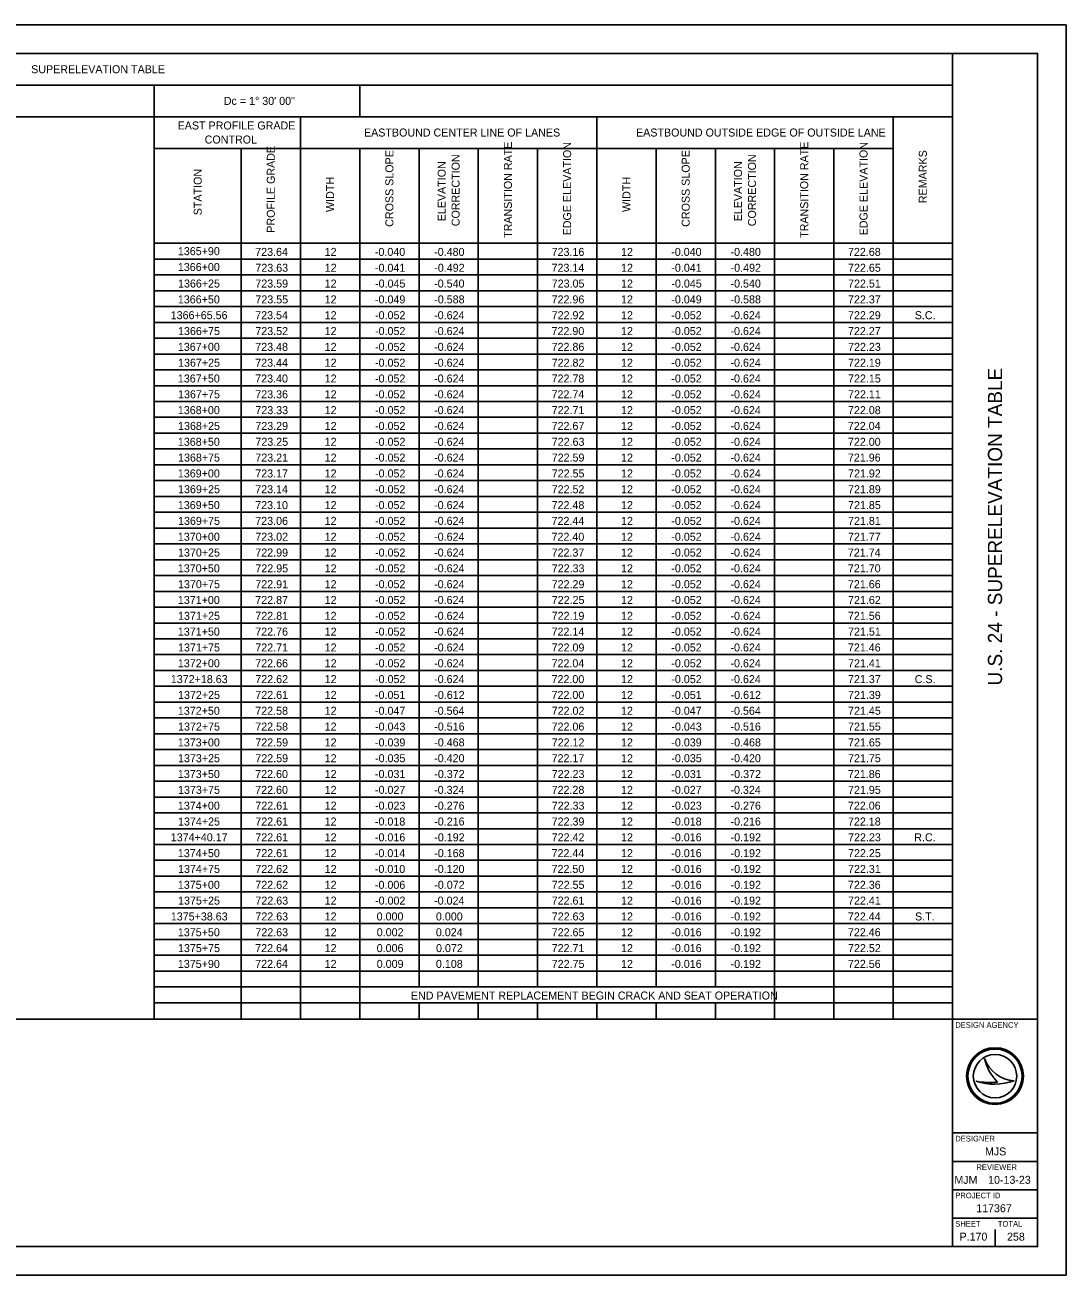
# Model space of a CAD drawing. Extents: x 0 to 34, y 0 to 22.
# Drawn here: x 15.67 to 34, y 0 to 22 of the extents above; entities that cross this region are included whole.
import ezdxf

# ---------------------------------------------------------------- set-up
doc = ezdxf.new("R2010")
doc.units = 0
for name, color, linetype in [('SH_Border', 7, 'Continuous'), ('SH_Cut_Line', 7, 'Continuous'), ('SH_Data', 7, 'Continuous'), ('SH_Text', 7, 'Continuous')]:
    doc.layers.add(name, color=color, linetype=linetype)

msp = doc.modelspace()

# ---------------------------------------------------------------- linework, layer by layer
at = {"layer": 'SH_Border'}
for p, q in [((32, 0.5), (32, 21.5)), ((32, 4.5), (33.5, 4.5)), ((32, 2.5), (33.5, 2.5)), ((32, 2), (33.5, 2)), ((32, 1.5), (33.5, 1.5)), ((32, 1), (33.5, 1))]:
    msp.add_line(p, q, dxfattribs=at)
msp.add_lwpolyline([(1.5, 21.5), (33.5, 21.5), (33.5, 0.5), (1.5, 0.5)], close=True, dxfattribs=at)
at = {"layer": 'SH_Cut_Line'}
msp.add_lwpolyline([(0, 0), (34, 0), (34, 22), (0, 22)], close=True, dxfattribs=at)
at = {"layer": 'SH_Data'}
for p, q in [((32.567, 3.81), (32.567, 3.81)), ((32.417, 3.41), (32.417, 3.41)), ((32.75, 3.5), (32.75, 3.5)), ((33.087, 3.419), (33.087, 3.419)), ((32.375, 0.675), (32.375, 0.675)), ((32.75, 0.5), (32.75, 0.8))]:
    msp.add_line(p, q, dxfattribs=at)
for radius in [0.5, 0.477, 0.477, 0.382]:
    msp.add_circle((32.75, 3.5), radius, dxfattribs=at)
for centre, radius, start, end in [((33.116, 3.998), 0.58, 198.9257, 198.9319), ((33.347, 3.97), 0.796, 191.6379, 191.6421), ((33.116, 3.998), 0.58, 198.9319, 267.1657), ((33.347, 3.97), 0.796, 191.6421, 226.0947), ((32.739, 4.37), 1.013, 251.4576, 290.0832), ((32.648, 4.654), 1.266, 259.4964, 259.4995), ((32.739, 4.37), 1.013, 251.4527, 251.4576), ((32.648, 4.654), 1.266, 259.4995, 276.6672)]:
    msp.add_arc(centre, radius, start, end, dxfattribs=at)
at = {"layer": 'SH_Text'}
for p, q in [((1.5, 21.5), (32, 21.5)), ((32, 21.5), (32, 4.5)), ((1.5, 20.943), (32, 20.943)), ((17.947, 20.943), (17.947, 4.5)), ((21.564, 20.943), (21.564, 20.386)), ((1.5, 20.386), (32, 20.386)), ((20.521, 20.386), (20.521, 18.158)), ((25.739, 20.386), (25.739, 18.158)), ((30.956, 20.386), (30.956, 18.158)), ((17.947, 19.829), (30.956, 19.829)), ((19.477, 19.829), (19.477, 18.158)), ((21.564, 19.829), (21.564, 18.158)), ((22.608, 19.829), (22.608, 18.158)), ((23.651, 19.829), (23.651, 18.158)), ((24.695, 19.829), (24.695, 18.158)), ((26.782, 19.829), (26.782, 18.158)), ((27.826, 19.829), (27.826, 18.158)), ((28.869, 19.829), (28.869, 18.158)), ((29.913, 19.829), (29.913, 18.158)), ((17.947, 18.158), (32, 18.158)), ((19.477, 18.158), (19.477, 4.5)), ((20.521, 18.158), (20.521, 4.5)), ((21.564, 18.158), (21.564, 4.5)), ((22.608, 18.158), (22.608, 5.071)), ((23.651, 18.158), (23.651, 5.071)), ((24.695, 18.158), (24.695, 5.071)), ((25.739, 18.158), (25.739, 5.071)), ((26.782, 18.158), (26.782, 5.071)), ((27.826, 18.158), (27.826, 5.071)), ((28.869, 18.158), (28.869, 4.5)), ((29.913, 18.158), (29.913, 4.5)), ((30.956, 18.158), (30.956, 4.5)), ((17.947, 17.88), (32, 17.88)), ((17.947, 17.602), (32, 17.602)), ((17.947, 17.323), (32, 17.323)), ((17.947, 17.045), (32, 17.045)), ((17.947, 16.766), (32, 16.766)), ((17.947, 16.488), (32, 16.488)), ((17.947, 16.209), (32, 16.209)), ((17.947, 15.931), (32, 15.931)), ((17.947, 15.652), (32, 15.652)), ((17.947, 15.374), (32, 15.374)), ((17.947, 15.095), (32, 15.095)), ((17.947, 14.817), (32, 14.817)), ((17.947, 14.538), (32, 14.538)), ((17.947, 14.26), (32, 14.26)), ((17.947, 13.982), (32, 13.982)), ((17.947, 13.703), (32, 13.703)), ((17.947, 13.425), (32, 13.425)), ((17.947, 13.146), (32, 13.146)), ((17.947, 12.868), (32, 12.868)), ((17.947, 12.589), (32, 12.589)), ((17.947, 12.311), (32, 12.311)), ((17.947, 12.032), (32, 12.032)), ((17.947, 11.754), (32, 11.754)), ((17.947, 11.475), (32, 11.475)), ((17.947, 11.197), (32, 11.197)), ((17.947, 10.919), (32, 10.919)), ((17.947, 10.64), (32, 10.64)), ((17.947, 10.362), (32, 10.362)), ((17.947, 10.083), (32, 10.083)), ((17.947, 9.805), (32, 9.805)), ((17.947, 9.526), (32, 9.526)), ((17.947, 9.248), (32, 9.248)), ((17.947, 8.969), (32, 8.969)), ((17.947, 8.691), (32, 8.691)), ((17.947, 8.412), (32, 8.412)), ((17.947, 8.134), (32, 8.134)), ((17.947, 7.855), (32, 7.855)), ((17.947, 7.577), (32, 7.577)), ((17.947, 7.299), (32, 7.299)), ((17.947, 7.02), (32, 7.02)), ((17.947, 6.742), (32, 6.742)), ((17.947, 6.463), (32, 6.463)), ((17.947, 6.185), (32, 6.185)), ((17.947, 5.906), (32, 5.906)), ((17.947, 5.628), (32, 5.628)), ((17.947, 5.349), (32, 5.349)), ((17.947, 5.071), (32, 5.071)), ((17.947, 4.792), (32, 4.792)), ((22.608, 4.792), (22.608, 4.5)), ((23.651, 4.792), (23.651, 4.5)), ((24.695, 4.792), (24.695, 4.5)), ((25.739, 4.792), (25.739, 4.5)), ((26.782, 4.792), (26.782, 4.5)), ((27.826, 4.792), (27.826, 4.5)), ((1.5, 4.5), (32, 4.5))]:
    msp.add_line(p, q, dxfattribs=at)

# ---------------------------------------------------------------- texts
at = {"layer": 'SH_Data'}
msp.add_text('U.S. 24 - SUPERELEVATION TABLE', height=0.25, rotation=90, dxfattribs=at).set_placement((32.875, 10.375))
for s, height, p in [('DESIGN AGENCY', 0.1, (32.05, 4.35)), ('DESIGNER', 0.1, (32.05, 2.35)), ('MJS', 0.14, (32.574, 2.105)), ('REVIEWER', 0.1, (32.422, 1.85)), ('MJM', 0.14, (32.035, 1.605)), ('10-13-23', 0.14, (32.629, 1.605)), ('PROJECT ID', 0.1, (32.05, 1.35)), ('117367', 0.14, (32.42, 1.105)), ('SHEET', 0.1, (32.05, 0.85)), ('TOTAL', 0.1, (32.8, 0.85)), ('P.170', 0.14, (32.126, 0.605)), ('258', 0.14, (32.962, 0.605))]:
    msp.add_text(s, height=height, dxfattribs=at).set_placement(p)
at = {"layer": 'SH_Text'}
for s, p in [('SUPERELEVATION TABLE', (15.779, 21.151)), ('Dc = 1° 30\' 00"', (19.171, 20.594)), ('EAST PROFILE GRADE ', (18.358, 20.161)), ('CONTROL', (18.834, 19.914)), ('EASTBOUND CENTER LINE OF LANES', (21.639, 20.037)), ('EASTBOUND OUTSIDE EDGE OF OUTSIDE LANE', (26.429, 20.037)), ('1365+90', (18.362, 17.949)), ('723.64', (19.724, 17.936)), ('12', (20.947, 17.936)), ('-0.040', (21.831, 17.936)), ('-0.480', (22.875, 17.936)), ('723.16', (24.943, 17.936)), ('12', (26.165, 17.936)), ('-0.040', (27.049, 17.936)), ('-0.480', (28.093, 17.936)), ('722.68', (30.161, 17.936)), ('1366+00', (18.362, 17.67)), ('723.63', (19.727, 17.657)), ('12', (20.947, 17.657)), ('-0.041', (21.833, 17.657)), ('-0.492', (22.877, 17.657)), ('723.14', (24.942, 17.657)), ('12', (26.165, 17.657)), ('-0.041', (27.051, 17.657)), ('-0.492', (28.095, 17.657)), ('722.65', (30.162, 17.657)), ('1366+25', (18.365, 17.379)), ('723.59', (19.726, 17.379)), ('12', (20.947, 17.379)), ('-0.045', (21.834, 17.379)), ('-0.540', (22.875, 17.379)), ('723.05', (24.945, 17.379)), ('12', (26.165, 17.379)), ('-0.045', (27.052, 17.379)), ('-0.540', (28.093, 17.379)), ('722.51', (30.162, 17.379)), ('1366+50', (18.362, 17.1)), ('723.55', (19.727, 17.1)), ('12', (20.947, 17.1)), ('-0.049', (21.833, 17.1)), ('-0.588', (22.876, 17.1)), ('722.96', (24.943, 17.1)), ('12', (26.165, 17.1)), ('-0.049', (27.051, 17.1)), ('-0.588', (28.094, 17.1)), ('722.37', (30.161, 17.1)), ('1366+65.56', (18.236, 16.822)), ('723.54', (19.724, 16.822)), ('12', (20.947, 16.822)), ('-0.052', (21.834, 16.822)), ('-0.624', (22.874, 16.822)), ('722.92', (24.944, 16.822)), ('12', (26.165, 16.822)), ('-0.052', (27.051, 16.822)), ('-0.624', (28.092, 16.822)), ('722.29', (30.162, 16.822)), ('S.C.', (31.336, 16.822)), ('1366+75', (18.365, 16.543)), ('723.52', (19.726, 16.543)), ('12', (20.947, 16.543)), ('-0.052', (21.834, 16.543)), ('-0.624', (22.874, 16.543)), ('722.90', (24.942, 16.543)), ('12', (26.165, 16.543)), ('-0.052', (27.051, 16.543)), ('-0.624', (28.092, 16.543)), ('722.27', (30.161, 16.543)), ('1367+00', (18.362, 16.265)), ('723.48', (19.725, 16.265)), ('12', (20.947, 16.265)), ('-0.052', (21.834, 16.265)), ('-0.624', (22.874, 16.265)), ('722.86', (24.943, 16.265)), ('12', (26.165, 16.265)), ('-0.052', (27.051, 16.265)), ('-0.624', (28.092, 16.265)), ('722.23', (30.163, 16.265)), ('1367+25', (18.365, 15.986)), ('723.44', (19.724, 15.986)), ('12', (20.947, 15.986)), ('-0.052', (21.834, 15.986)), ('-0.624', (22.874, 15.986)), ('722.82', (24.944, 15.986)), ('12', (26.165, 15.986)), ('-0.052', (27.051, 15.986)), ('-0.624', (28.092, 15.986)), ('722.19', (30.162, 15.986)), ('1367+50', (18.362, 15.708)), ('723.40', (19.724, 15.708)), ('12', (20.947, 15.708)), ('-0.052', (21.834, 15.708)), ('-0.624', (22.874, 15.708)), ('722.78', (24.943, 15.708)), ('12', (26.165, 15.708)), ('-0.052', (27.051, 15.708)), ('-0.624', (28.092, 15.708)), ('722.15', (30.162, 15.708)), ('1367+75', (18.365, 15.43)), ('723.36', (19.725, 15.43)), ('12', (20.947, 15.43)), ('-0.052', (21.834, 15.43)), ('-0.624', (22.874, 15.43)), ('722.74', (24.942, 15.43)), ('12', (26.165, 15.43)), ('-0.052', (27.051, 15.43)), ('-0.624', (28.092, 15.43)), ('722.11', (30.162, 15.43)), ('1368+00', (18.362, 15.151)), ('723.33', (19.727, 15.151)), ('12', (20.947, 15.151)), ('-0.052', (21.834, 15.151)), ('-0.624', (22.874, 15.151)), ('722.71', (24.944, 15.151)), ('12', (26.165, 15.151)), ('-0.052', (27.051, 15.151)), ('-0.624', (28.092, 15.151)), ('722.08', (30.161, 15.151)), ('1368+25', (18.365, 14.873)), ('723.29', (19.726, 14.873)), ('12', (20.947, 14.873)), ('-0.052', (21.834, 14.873)), ('-0.624', (22.874, 14.873)), ('722.67', (24.943, 14.873)), ('12', (26.165, 14.873)), ('-0.052', (27.051, 14.873)), ('-0.624', (28.092, 14.873)), ('722.04', (30.159, 14.873)), ('1368+50', (18.362, 14.594)), ('723.25', (19.727, 14.594)), ('12', (20.947, 14.594)), ('-0.052', (21.834, 14.594)), ('-0.624', (22.874, 14.594)), ('722.63', (24.945, 14.594)), ('12', (26.165, 14.594)), ('-0.052', (27.051, 14.594)), ('-0.624', (28.092, 14.594)), ('722.00', (30.16, 14.594)), ('1368+75', (18.365, 14.316)), ('723.21', (19.726, 14.316)), ('12', (20.947, 14.316)), ('-0.052', (21.834, 14.316)), ('-0.624', (22.874, 14.316)), ('722.59', (24.944, 14.316)), ('12', (26.165, 14.316)), ('-0.052', (27.051, 14.316)), ('-0.624', (28.092, 14.316)), ('721.96', (30.16, 14.316)), ('1369+00', (18.362, 14.037)), ('723.17', (19.725, 14.037)), ('12', (20.947, 14.037)), ('-0.052', (21.834, 14.037)), ('-0.624', (22.874, 14.037)), ('722.55', (24.945, 14.037)), ('12', (26.165, 14.037)), ('-0.052', (27.051, 14.037)), ('-0.624', (28.092, 14.037)), ('721.92', (30.162, 14.037)), ('1369+25', (18.365, 13.759)), ('723.14', (19.724, 13.759)), ('12', (20.947, 13.759)), ('-0.052', (21.834, 13.759)), ('-0.624', (22.874, 13.759)), ('722.52', (24.944, 13.759)), ('12', (26.165, 13.759)), ('-0.052', (27.051, 13.759)), ('-0.624', (28.092, 13.759)), ('721.89', (30.162, 13.759)), ('1369+50', (18.362, 13.48)), ('723.10', (19.724, 13.48)), ('12', (20.947, 13.48)), ('-0.052', (21.834, 13.48)), ('-0.624', (22.874, 13.48)), ('722.48', (24.943, 13.48)), ('12', (26.165, 13.48)), ('-0.052', (27.051, 13.48)), ('-0.624', (28.092, 13.48)), ('721.85', (30.162, 13.48)), ('1369+75', (18.365, 13.202)), ('723.06', (19.725, 13.202)), ('12', (20.947, 13.202)), ('-0.052', (21.834, 13.202)), ('-0.624', (22.874, 13.202)), ('722.44', (24.942, 13.202)), ('12', (26.165, 13.202)), ('-0.052', (27.051, 13.202)), ('-0.624', (28.092, 13.202)), ('721.81', (30.162, 13.202)), ('1370+00', (18.362, 12.923)), ('723.02', (19.726, 12.923)), ('12', (20.947, 12.923)), ('-0.052', (21.834, 12.923)), ('-0.624', (22.874, 12.923)), ('722.40', (24.942, 12.923)), ('12', (26.165, 12.923)), ('-0.052', (27.051, 12.923)), ('-0.624', (28.092, 12.923)), ('721.77', (30.161, 12.923)), ('1370+25', (18.365, 12.645)), ('722.99', (19.726, 12.645)), ('12', (20.947, 12.645)), ('-0.052', (21.834, 12.645)), ('-0.624', (22.874, 12.645)), ('722.37', (24.943, 12.645)), ('12', (26.165, 12.645)), ('-0.052', (27.051, 12.645)), ('-0.624', (28.092, 12.645)), ('721.74', (30.159, 12.645)), ('1370+50', (18.362, 12.367)), ('722.95', (19.727, 12.367)), ('12', (20.947, 12.367)), ('-0.052', (21.834, 12.367)), ('-0.624', (22.874, 12.367)), ('722.33', (24.945, 12.367)), ('12', (26.165, 12.367)), ('-0.052', (27.051, 12.367)), ('-0.624', (28.092, 12.367)), ('721.70', (30.16, 12.367)), ('1370+75', (18.365, 12.088)), ('722.91', (19.726, 12.088)), ('12', (20.947, 12.088)), ('-0.052', (21.834, 12.088)), ('-0.624', (22.874, 12.088)), ('722.29', (24.944, 12.088)), ('12', (26.165, 12.088)), ('-0.052', (27.051, 12.088)), ('-0.624', (28.092, 12.088)), ('721.66', (30.16, 12.088)), ('1371+00', (18.362, 11.81)), ('722.87', (19.725, 11.81)), ('12', (20.947, 11.81)), ('-0.052', (21.834, 11.81)), ('-0.624', (22.874, 11.81)), ('722.25', (24.945, 11.81)), ('12', (26.165, 11.81)), ('-0.052', (27.051, 11.81)), ('-0.624', (28.092, 11.81)), ('721.62', (30.162, 11.81)), ('1371+25', (18.365, 11.531)), ('722.81', (19.726, 11.531)), ('12', (20.947, 11.531)), ('-0.052', (21.834, 11.531)), ('-0.624', (22.874, 11.531)), ('722.19', (24.944, 11.531)), ('12', (26.165, 11.531)), ('-0.052', (27.051, 11.531)), ('-0.624', (28.092, 11.531)), ('721.56', (30.16, 11.531)), ('1371+50', (18.362, 11.253)), ('722.76', (19.725, 11.253)), ('12', (20.947, 11.253)), ('-0.052', (21.834, 11.253)), ('-0.624', (22.874, 11.253)), ('722.14', (24.942, 11.253)), ('12', (26.165, 11.253)), ('-0.052', (27.051, 11.253)), ('-0.624', (28.092, 11.253)), ('721.51', (30.162, 11.253)), ('1371+75', (18.365, 10.974)), ('722.71', (19.726, 10.974)), ('12', (20.947, 10.974)), ('-0.052', (21.834, 10.974)), ('-0.624', (22.874, 10.974)), ('722.09', (24.944, 10.974)), ('12', (26.165, 10.974)), ('-0.052', (27.051, 10.974)), ('-0.624', (28.092, 10.974)), ('721.46', (30.16, 10.974)), ('1372+00', (18.362, 10.696)), ('722.66', (19.725, 10.696)), ('12', (20.947, 10.696)), ('-0.052', (21.834, 10.696)), ('-0.624', (22.874, 10.696)), ('722.04', (24.942, 10.696)), ('12', (26.165, 10.696)), ('-0.052', (27.051, 10.696)), ('-0.624', (28.092, 10.696)), ('721.41', (30.162, 10.696)), ('1372+18.63', (18.238, 10.417)), ('722.62', (19.726, 10.417)), ('12', (20.947, 10.417)), ('-0.052', (21.834, 10.417)), ('-0.624', (22.874, 10.417)), ('722.00', (24.942, 10.417)), ('12', (26.165, 10.417)), ('-0.052', (27.051, 10.417)), ('-0.624', (28.092, 10.417)), ('721.37', (30.161, 10.417)), ('C.S.', (31.336, 10.417)), ('1372+25', (18.365, 10.139)), ('722.61', (19.726, 10.139)), ('12', (20.947, 10.139)), ('-0.051', (21.833, 10.139)), ('-0.612', (22.877, 10.139)), ('722.00', (24.942, 10.139)), ('12', (26.165, 10.139)), ('-0.051', (27.051, 10.139)), ('-0.612', (28.095, 10.139)), ('721.39', (30.162, 10.139)), ('1372+50', (18.362, 9.86)), ('722.58', (19.725, 9.86)), ('12', (20.947, 9.86)), ('-0.047', (21.833, 9.86)), ('-0.564', (22.874, 9.86)), ('722.02', (24.944, 9.86)), ('12', (26.165, 9.86)), ('-0.047', (27.05, 9.86)), ('-0.564', (28.092, 9.86)), ('721.45', (30.162, 9.86)), ('1372+75', (18.365, 9.582)), ('722.58', (19.725, 9.582)), ('12', (20.947, 9.582)), ('-0.043', (21.834, 9.582)), ('-0.516', (22.876, 9.582)), ('722.06', (24.943, 9.582)), ('12', (26.165, 9.582)), ('-0.043', (27.052, 9.582)), ('-0.516', (28.093, 9.582)), ('721.55', (30.162, 9.582)), ('1373+00', (18.362, 9.303)), ('722.59', (19.726, 9.303)), ('12', (20.947, 9.303)), ('-0.039', (21.833, 9.303)), ('-0.468', (22.876, 9.303)), ('722.12', (24.944, 9.303)), ('12', (26.165, 9.303)), ('-0.039', (27.051, 9.303)), ('-0.468', (28.094, 9.303)), ('721.65', (30.162, 9.303)), ('1373+25', (18.365, 9.025)), ('722.59', (19.726, 9.025)), ('12', (20.947, 9.025)), ('-0.035', (21.834, 9.025)), ('-0.420', (22.875, 9.025)), ('722.17', (24.943, 9.025)), ('12', (26.165, 9.025)), ('-0.035', (27.052, 9.025)), ('-0.420', (28.093, 9.025)), ('721.75', (30.162, 9.025)), ('1373+50', (18.362, 8.747)), ('722.60', (19.724, 8.747)), ('12', (20.947, 8.747)), ('-0.031', (21.833, 8.747)), ('-0.372', (22.877, 8.747)), ('722.23', (24.945, 8.747)), ('12', (26.165, 8.747)), ('-0.031', (27.051, 8.747)), ('-0.372', (28.095, 8.747)), ('721.86', (30.16, 8.747)), ('1373+75', (18.365, 8.468)), ('722.60', (19.724, 8.468)), ('12', (20.947, 8.468)), ('-0.027', (21.833, 8.468)), ('-0.324', (22.874, 8.468)), ('722.28', (24.943, 8.468)), ('12', (26.165, 8.468)), ('-0.027', (27.05, 8.468)), ('-0.324', (28.092, 8.468)), ('721.95', (30.162, 8.468)), ('1374+00', (18.362, 8.19)), ('722.61', (19.726, 8.19)), ('12', (20.947, 8.19)), ('-0.023', (21.834, 8.19)), ('-0.276', (22.876, 8.19)), ('722.33', (24.945, 8.19)), ('12', (26.165, 8.19)), ('-0.023', (27.052, 8.19)), ('-0.276', (28.093, 8.19)), ('722.06', (30.16, 8.19)), ('1374+25', (18.365, 7.911)), ('722.61', (19.726, 7.911)), ('12', (20.947, 7.911)), ('-0.018', (21.832, 7.911)), ('-0.216', (22.876, 7.911)), ('722.39', (24.944, 7.911)), ('12', (26.165, 7.911)), ('-0.018', (27.05, 7.911)), ('-0.216', (28.093, 7.911)), ('722.18', (30.161, 7.911)), ('1374+40.17', (18.237, 7.633)), ('722.61', (19.726, 7.633)), ('12', (20.947, 7.633)), ('-0.016', (21.832, 7.633)), ('-0.192', (22.877, 7.633)), ('722.42', (24.944, 7.633)), ('12', (26.165, 7.633)), ('-0.016', (27.05, 7.633)), ('-0.192', (28.095, 7.633)), ('722.23', (30.163, 7.633)), ('R.C.', (31.328, 7.633)), ('1374+50', (18.362, 7.354)), ('722.61', (19.726, 7.354)), ('12', (20.947, 7.354)), ('-0.014', (21.831, 7.354)), ('-0.168', (22.876, 7.354)), ('722.44', (24.942, 7.354)), ('12', (26.165, 7.354)), ('-0.016', (27.05, 7.354)), ('-0.192', (28.095, 7.354)), ('722.25', (30.162, 7.354)), ('1374+75', (18.365, 7.076)), ('722.62', (19.726, 7.076)), ('12', (20.947, 7.076)), ('-0.010', (21.831, 7.076)), ('-0.120', (22.875, 7.076)), ('722.50', (24.942, 7.076)), ('12', (26.165, 7.076)), ('-0.016', (27.05, 7.076)), ('-0.192', (28.095, 7.076)), ('722.31', (30.162, 7.076)), ('1375+00', (18.362, 6.797)), ('722.62', (19.726, 6.797)), ('12', (20.947, 6.797)), ('-0.006', (21.832, 6.797)), ('-0.072', (22.877, 6.797)), ('722.55', (24.945, 6.797)), ('12', (26.165, 6.797)), ('-0.016', (27.05, 6.797)), ('-0.192', (28.095, 6.797)), ('722.36', (30.16, 6.797)), ('1375+25', (18.365, 6.519)), ('722.63', (19.727, 6.519)), ('12', (20.947, 6.519)), ('-0.002', (21.834, 6.519)), ('-0.024', (22.874, 6.519)), ('722.61', (24.944, 6.519)), ('12', (26.165, 6.519)), ('-0.016', (27.05, 6.519)), ('-0.192', (28.095, 6.519)), ('722.41', (30.162, 6.519)), ('1375+38.63', (18.238, 6.24)), ('722.63', (19.727, 6.24)), ('12', (20.947, 6.24)), ('0.000', (21.862, 6.24)), ('0.000', (22.906, 6.24)), ('722.63', (24.945, 6.24)), ('12', (26.165, 6.24)), ('-0.016', (27.05, 6.24)), ('-0.192', (28.095, 6.24)), ('722.44', (30.159, 6.24)), ('S.T.', (31.341, 6.24)), ('1375+50', (18.362, 5.962)), ('722.63', (19.727, 5.962)), ('12', (20.947, 5.962)), ('0.002', (21.864, 5.962)), ('0.024', (22.905, 5.962)), ('722.65', (24.945, 5.962)), ('12', (26.165, 5.962)), ('-0.016', (27.05, 5.962)), ('-0.192', (28.095, 5.962)), ('722.46', (30.16, 5.962)), ('1375+75', (18.365, 5.683)), ('722.64', (19.724, 5.683)), ('12', (20.947, 5.683)), ('0.006', (21.863, 5.683)), ('0.072', (22.908, 5.683)), ('722.71', (24.944, 5.683)), ('12', (26.165, 5.683)), ('-0.016', (27.05, 5.683)), ('-0.192', (28.095, 5.683)), ('722.52', (30.162, 5.683)), ('1375+90', (18.362, 5.405)), ('722.64', (19.724, 5.405)), ('12', (20.947, 5.405)), ('0.009', (21.864, 5.405)), ('0.108', (22.906, 5.405)), ('722.75', (24.945, 5.405)), ('12', (26.165, 5.405)), ('-0.016', (27.05, 5.405)), ('-0.192', (28.095, 5.405)), ('722.56', (30.16, 5.405)), ('END PAVEMENT REPLACEMENT BEGIN CRACK AND SEAT OPERATION', (22.465, 4.848))]:
    msp.add_text(s, height=0.1409, dxfattribs=at).set_placement(p)
for s, height, p in [('PROFILE GRADE', 0.14081, (20.069, 18.344)), ('TRANSITION RATE', 0.14081, (24.244, 18.253)), ('EDGE ELEVATION', 0.14081, (25.287, 18.298)), ('TRANSITION RATE', 0.14081, (29.461, 18.253)), ('EDGE ELEVATION', 0.14081, (30.505, 18.298)), ('CROSS SLOPE', 0.14081, (22.157, 18.448)), ('ELEVATION ', 0.1408, (23.077, 18.545)), ('CORRECTION', 0.1408, (23.323, 18.458)), ('CROSS SLOPE', 0.14081, (27.374, 18.448)), ('ELEVATION ', 0.1408, (28.295, 18.545)), ('CORRECTION', 0.1408, (28.541, 18.458)), ('REMARKS', 0.1408, (31.549, 18.865)), ('STATION', 0.1408, (18.782, 18.651)), ('WIDTH', 0.1408, (21.113, 18.709)), ('WIDTH', 0.1408, (26.331, 18.709))]:
    msp.add_text(s, height=height, rotation=90, dxfattribs=at).set_placement(p)

doc.saveas('drawing.dxf')
